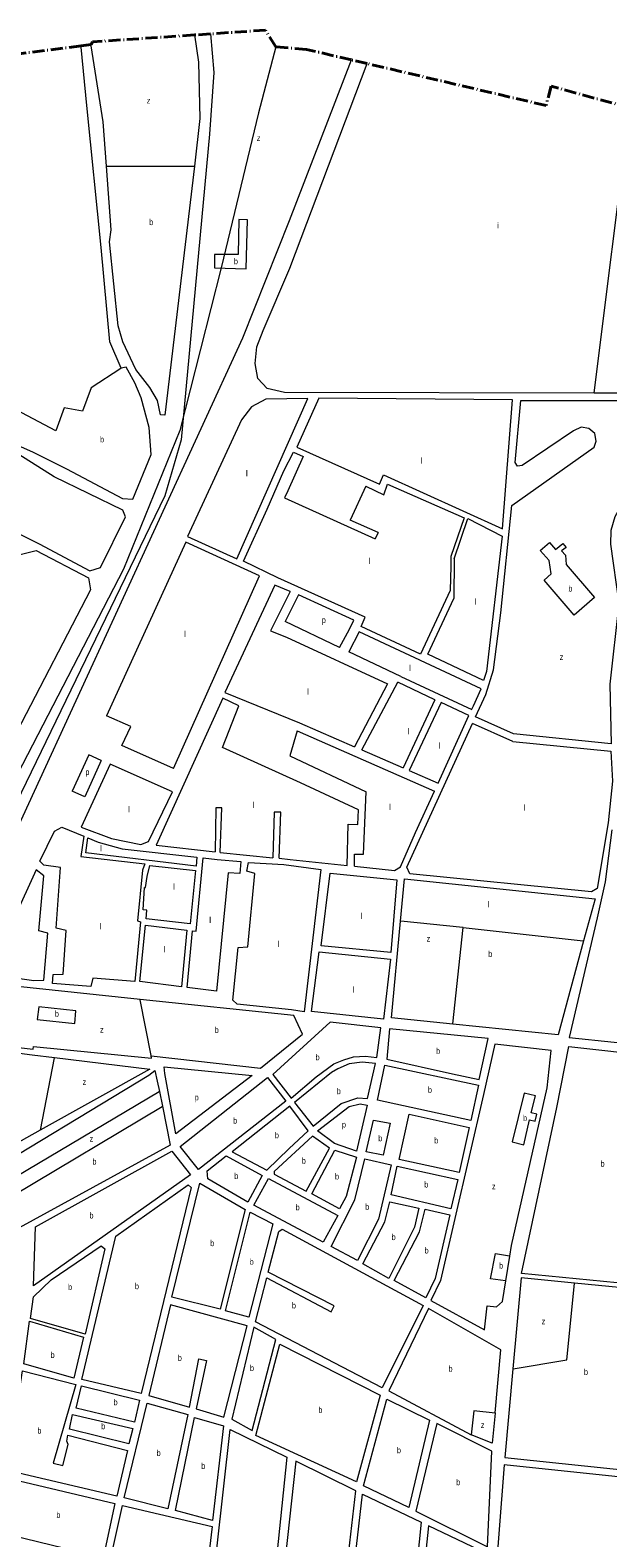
# Model space of a CAD drawing. Extents: x 639657 to 671642, y 222838 to 252123.
# Drawn here: x 650568 to 651529, y 249227 to 251734 of the extents above; entities that cross this region are included whole.
import ezdxf

# ---------------------------------------------------------------- set-up
doc = ezdxf.new("R2010")
doc.units = 0
doc.header["$LTSCALE"] = 4
doc.linetypes.add('DOT_DASHED', pattern=[7.7, 5, -1.2, 0.3, -1.2])
for name, color, linetype, lineweight in [('1', 7, 'Continuous', 13), ('21', 7, 'Continuous', 13), ('4', 7, 'DOT_DASHED', 40), ('57', 7, 'Continuous', 35)]:
    doc.layers.add(name, color=color, linetype=linetype, lineweight=lineweight)
doc.layers.add('7', color=7, linetype='Continuous')

msp = doc.modelspace()

# ---------------------------------------------------------------- linework, layer by layer
at = {"layer": '1'}
for p, q in [((651022.534, 251025.498), (650996.831, 250968.191)), ((650996.831, 250968.191), (650991.702, 250956.694)), ((651126.739, 250976.285), (651100.554, 250919.799)), ((650991.702, 250956.694), (651142.14, 250888.441)), ((651147.339, 250899.362), (651100.554, 250919.799)), ((651273.44, 250855.25), (651296.38, 250922.23)), ((651147.339, 250899.362), (651142.14, 250888.441)), ((651273.44, 250855.25), (651273.412, 250789.632)), ((651000.903, 250801.258), (650968.026, 250735.47)), ((651014.698, 250795.242), (650992.53, 250750.887)), ((651083.049, 250708.025), (650992.53, 250750.887)), ((651083.049, 250708.025), (651099.383, 250738.481)), ((651115.519, 250734.12), (651098.663, 250700.632)), ((651184.96, 250659.77), (651098.663, 250700.632)), ((651184.96, 250659.77), (651302.849, 250604.591)), ((651119.913, 250537.737), (651179.824, 250650.134)), ((651241.761, 250621.112), (651179.824, 250650.134)), ((651241.761, 250621.112), (651188.624, 250507.908)), ((651251.99, 250616.319), (651199.021, 250503.394)), ((651298.29, 250594.624), (651251.99, 250616.319)), ((651303.203, 250605.365), (651305.776, 250610.992)), ((651247.037, 250482.549), (651298.29, 250594.624)), ((651302.849, 250604.591), (651303.203, 250605.365)), ((651372.6, 250564.2), (651309.313, 250592.462)), ((651012.526, 250569.33), (651240.906, 250469.143)), ((651016.41, 250582.67), (651107.856, 250542.971)), ((651371.4, 250551.74), (651304.221, 250581.317)), ((651119.913, 250537.737), (651188.624, 250507.908)), ((650701.425, 250513.803), (650653.418, 250409.014)), ((650805.341, 250468.037), (650701.425, 250513.803)), ((651199.021, 250503.394), (651247.037, 250482.549)), ((650845.891, 250359.361), (650844.357, 250344.121)), ((650884.404, 250366.79), (650971.905, 250358.392)), ((650767.52, 250345.44), (650843.654, 250337.132)), ((651446.49, 250063.62), (651271.221, 250081.624)), ((650571.8, 250030.6), (650608.784, 250026.134)), ((651385.13, 249659.49), (651371.395, 249508.303)), ((651341.863, 249435.427), (651351.37, 249539.82)), ((651341.863, 249435.427), (651341.776, 249434.557))]:
    msp.add_line(p, q, dxfattribs=at)
for points in [[(650868.558, 251728.311), (650873.94, 251663.96), (650866.91, 251561.41), (650819.54, 251053.22), (650792.31, 250960.32), (650503.6, 250364.17), (650397.41, 250169.26), (650436.51, 250167.22), (650922.17, 251222.64), (650999.81, 251417.78), (651103.042, 251685.015)], [(650841.676, 251726.488), (650848.34, 251681.08), (650850.95, 251587.37), (650841.626, 251508.588)], [(650719.99, 251172.42), (650701.18, 251216.42), (650686.79, 251372.84), (650662.52, 251609.21), (650653.43, 251706.344), (650653.243, 251708.344)], [(650695.569, 251508.588), (650690.09, 251582.2), (650670.087, 251708.47), (650669.77, 251710.47)], [(651506.632, 251130.988), (650991.55, 251131.69), (650962.56, 251138.73), (650947.27, 251155.44), (650942.47, 251180.36), (650945.4, 251207.87), (650955.85, 251235.19), (651000.24, 251338.48), (651129.262, 251678.874)], [(651639.899, 251585.126), (651635.23, 251566.32), (651635.56, 251556.65), (651642.6, 251551.42), (651693.7, 251527.7), (651600.79, 251130.86), (651506.632, 251130.988)], [(650841.626, 251508.588), (650792.58, 251094.19), (650785.49, 251094.6), (650780.27, 251118.65), (650767.33, 251140.32), (650744.05, 251170.12), (650722.66, 251216.48), (650715.07, 251242.89), (650700.72, 251382.55), (650703.46, 251402.55), (650695.569, 251508.588)], [(650438.466, 251107.379), (650456.62, 251099.69), (650513.21, 251067.4), (650542.48, 251046.85), (650573.67, 251032.54), (650628.95, 251004.98), (650721.88, 250955.61), (650739.06, 250954.58), (650769.57, 251029.02), (650766.65, 251073.7), (650752.99, 251122.87), (650742.61, 251148.2), (650728.14, 251174.16), (650719.99, 251172.42)], [(650334.663, 250945.634), (650451.28, 250936.15), (650517.94, 250912.7), (650583.33, 250880.44), (650667.87, 250835.56), (650685.47, 250841.19), (650727.11, 250925.33), (650722.36, 250936.05), (650608.15, 250991.81), (650479.68, 251072.68), (650442.25, 251091.7), (650405.34, 251107.088), (650366.98, 251123.08)], [(651375.4, 251015.45), (651384.83, 251118.69), (651600.45, 251118.4), (651570.94, 250984.21), (651564.1, 250966.67), (651540.69, 250925.01), (651534.23, 250902.73), (651533.99, 250879.52), (651547.35, 250780.97), (651532.62, 250647.02), (651534.79, 250547.7), (651372.6, 250564.2)], [(651309.313, 250592.462), (651326.27, 250629.58), (651338.94, 250670.72), (651351.54, 250765.36), (651369.5, 250943.96), (651506.45, 251040.96), (651509.77, 251051.02), (651507.54, 251063.72), (651497.96, 251072.2), (651485.1, 251074.05), (651471.94, 251068.17), (651386.94, 251010.6), (651378.99, 251009.4), (651375.4, 251015.45)], [(650962.68, 250938.03), (650990.51, 251001.51), (651006.65, 251033), (651022.534, 251025.498)], [(651126.739, 250976.285), (651156.88, 250962.05), (651163.07, 250979.61), (651290.37, 250923.59), (651268.42, 250859.42)], [(651267.083, 250802.702), (651217.67, 250696.68), (651119.16, 250742.82), (651125.55, 250758.45), (650980.57, 250823.59), (650923.19, 250851.76), (650962.68, 250938.03)], [(651296.38, 250922.23), (651353.73, 250892.98), (651327.75, 250667.82), (651322.54, 250653.03), (651230.132, 250697.074), (651273.412, 250789.632)], [(650468.73, 250842.08), (650578.63, 250869.25), (650665.75, 250823.52), (650669.03, 250803.98), (650546.19, 250567.94)], [(650806.853, 250506.475), (650950.11, 250827.13), (650827.53, 250882.85), (650695.622, 250594.447)], [(651268.42, 250859.42), (651268.039, 250843.28), (651267.083, 250802.702)], [(651000.903, 250801.258), (650975.28, 250811.52), (650892.23, 250632.96), (651016.41, 250582.67)], [(651099.383, 250738.481), (651106.82, 250753.48), (651014.698, 250795.242)], [(650968.026, 250735.47), (650994.92, 250725.09), (651162.82, 250647.6), (651107.856, 250542.971)], [(651305.776, 250610.992), (651318.563, 250638.954), (651115.519, 250734.12)], [(651114.325, 250438.006), (651018.39, 250483.12), (650888.2, 250541.65), (650915.49, 250610.69), (650888.82, 250623.72), (650778.27, 250379.37), (650875.99, 250367.893)], [(650806.853, 250506.475), (650721.023, 250545.187), (650735.723, 250576.702), (650695.622, 250594.447)], [(651012.526, 250569.33), (651000.5, 250528.04), (651127.588, 250468.048)], [(651371.4, 250551.74), (651534.23, 250535.66), (651536.92, 250485.77), (651529.73, 250416.63), (651511.37, 250307.39), (651501.86, 250301.9), (651199.81, 250331.45), (651195.2, 250342.68), (651304.221, 250581.317)], [(650686.723, 250520.278), (650665.895, 250529.451), (650638.271, 250469.056)], [(650686.723, 250520.278), (650659.421, 250459.746), (650638.271, 250469.056)], [(650653.418, 250409.014), (650703.5, 250390.32), (650752.71, 250380.58), (650765.37, 250385.34), (650805.341, 250468.037)], [(651107.783, 250344.088), (651174.74, 250336.87), (651184.47, 250343.22), (651209.35, 250400.14), (651240.906, 250469.143)], [(651107.783, 250344.088), (651107.783, 250364.5), (651123.184, 250364.5), (651127.588, 250468.048)], [(650884.404, 250366.79), (650887.277, 250441.537), (650877.477, 250441.537), (650875.99, 250367.893)], [(650982.397, 250357.386), (650985.28, 250433.833), (650974.08, 250433.833), (650971.905, 250358.392)], [(651095.834, 250345.376), (651097.283, 250414.224), (651113.384, 250413.523), (651114.325, 250438.006)], [(650759.24, 250348.16), (650755.19, 250337.41), (650747.06, 250253.41), (650751.79, 250251.49), (650742.62, 250152.66), (650672.59, 250158.04), (650669.41, 250144.28), (650605.39, 250149.46), (650606.85, 250164.29), (650623.39, 250164.55), (650628.33, 250237.38), (650611.57, 250240.98), (650619.22, 250342.17), (650591.29, 250346.17), (650584.83, 250352.81), (650608.96, 250402.5), (650621.39, 250409.41), (650657.479, 250394.247)], [(650657.479, 250394.247), (650652.663, 250360.516), (650759.24, 250348.16)], [(650844.357, 250344.121), (650661.297, 250366.275), (650664.625, 250391.245)], [(650664.625, 250391.245), (650681.82, 250384.02), (650721.59, 250373.18), (650845.891, 250359.361)], [(651536.06, 250404.859), (651524.81, 250318.44), (651511.7, 250258.59), (651464.84, 250059.32), (651614.58, 250043.81), (651636.5, 250260.1), (651650.02, 250259.53), (651659.791, 250403.293)], [(650761.257, 250256.55), (650762.69, 250271.06), (650756.67, 250271.48), (650758.93, 250309.07), (650760.43, 250309.07), (650763.17, 250326.91), (650767.52, 250345.44)], [(650843.654, 250337.132), (650834.706, 250248.217), (650761.257, 250256.55)], [(650829.547, 250142.518), (650838.304, 250236.699), (650844.78, 250235.979), (650856.483, 250358.183)], [(650856.483, 250358.183), (650879.45, 250355.63), (650919.02, 250352.29), (650917.14, 250332.31), (650898.03, 250333.11), (650878.18, 250136.22), (650829.547, 250142.518)], [(650982.397, 250357.386), (651001, 250355.6), (651095.834, 250345.376)], [(651184.473, 250252.815), (651190.93, 250323.22), (651508.03, 250289.86), (651489.044, 250220.063), (651446.49, 250063.62)], [(650820.036, 250143.75), (650751, 250152.69), (650760.211, 250245.953)], [(650760.211, 250245.953), (650828.95, 250238.138), (650820.036, 250143.75)], [(651271.221, 250081.624), (651169.73, 250092.05), (651184.473, 250252.815)], [(650751.211, 250122.705), (650494.56, 250149.78), (650485.12, 250144.17), (650455.69, 250072.56), (650458.95, 250059.69), (650470.57, 250051.77), (650573.28, 250040.05), (650574.12, 250044.56), (650770.49, 250025.17), (650769.62, 250028.82), (650951.57, 250008.54)], [(650951.57, 250008.54), (651021.69, 250064.72), (651006.91, 250095.73), (650751.211, 250122.705)], [(650584.9, 249905.065), (650360.9, 249779.99), (650325.29, 249801.35), (650428.99, 250010.48), (650442.46, 250043.75), (650465.65, 250044.67), (650571.8, 250030.6)], [(651341.51, 250048.57), (651322.64, 249964.55), (651250.77, 249655.24), (651235.17, 249622.05), (651324.25, 249573.12), (651328.42, 249613.1), (651343.89, 249611.28), (651353.91, 249620.59), (651359.472, 249654.835), (651366.157, 249695.986)], [(651366.157, 249695.986), (651369, 249713.49), (651428.17, 249975.81), (651435.25, 250037.71), (651341.51, 250048.57)], [(650608.784, 250026.134), (650767.42, 250006.98), (650584.9, 249905.065)], [(650788.395, 249945.143), (650801.61, 249880.4), (650520.77, 249726.86), (650468.951, 249816.967), (650765.83, 249996.5), (650775.7, 250004.36)], [(650775.7, 250004.36), (650779.91, 249986.71), (650783.434, 249969.447), (650788.395, 249945.143)], [(651371.395, 249508.303), (651358.01, 249360.95), (651586.01, 249337.13), (651611.36, 249517.32), (651610.78, 249637.37), (651473.892, 249650.789), (651385.13, 249659.49)], [(651351.37, 249539.82), (651231.2, 249608.71), (651164.95, 249471.6), (651302.1, 249398.54)], [(651341.776, 249434.557), (651336.784, 249384.617), (651302.1, 249398.54)], [(651356.83, 249348.91), (651339.856, 249126.621), (651334.656, 249058.524), (651331.824, 249021.434)], [(651391.051, 248956.455), (651492.1, 248946.95), (651582.89, 249325.08), (651356.83, 249348.91)]]:
    msp.add_lwpolyline(points, dxfattribs=at)
for points in [[(650912.01, 250855.38), (651030.58, 251122.08), (650960.46, 251121.1), (650936.66, 251108.35), (650920.18, 251086.6), (650830.08, 250892.75)], [(651370.88, 251119.91), (651048.58, 251122.37), (651011.89, 251041.32), (651149.54, 250979.53), (651156.14, 250994.93), (651354.28, 250905.01)], [(650508.26, 250163.57), (650574.66, 250154.1), (650591.41, 250155.01), (650597.63, 250232.99), (650582.8, 250236.6), (650591.34, 250328.13), (650578.43, 250338.4), (650502.23, 250171.5)], [(650931.91, 250350.61), (650990.15, 250347.06), (651051.93, 250338.62), (651024.23, 250102.36), (651002.96, 250105.38), (650912.61, 250114.73), (650905.72, 250121.58), (650914.7, 250209.02), (650930.8, 250210.35), (650942.05, 250332.38), (650928.73, 250335.99)], [(651168.34, 250200.88), (651052.48, 250211.74), (651067.54, 250332.87), (651178.46, 250321.41)], [(651155.96, 250090.04), (651036.69, 250102.66), (651048.94, 250202.1), (651167.58, 250189.71)], [(651067.2, 250084.71), (650971.85, 249997.94), (651002.34, 249958.61), (651044.06, 249993.75), (651073.53, 250015.4), (651090.14, 250022.32), (651106.09, 250027.32), (651126.5, 250028.4), (651144.95, 250026.28), (651151.51, 250075.46)], [(651161.67, 250023.53), (651270.71, 249998.79), (651315.49, 249989.68), (651330.44, 250057.5), (651166.31, 250074.02)], [(651608.83, 250028.6), (651613.28, 249644.75), (651385.5, 249667.22), (651444.4, 249943.05), (651464.25, 250044.49)], [(650791.36, 250010.42), (650937.66, 249996.33), (650810.96, 249899.26), (650792.61, 249999.5)], [(651080.31, 250007.58), (651069.92, 250001.23), (651008.4, 249951.26), (651039.23, 249911.99), (651085.91, 249949.49), (651113.52, 249958.94), (651129.84, 249958.2), (651142.9, 250016.21), (651120.81, 250018.35), (651098.87, 250015.35)], [(651145.97, 249955.1), (651158.37, 250013.31), (651314.29, 249980.01), (651301.71, 249921.5)], [(650993.71, 249953.45), (650848.67, 249839.76), (650817.72, 249878.38), (650963.19, 249992.72)], [(651031.14, 249903.98), (651000.39, 249945.14), (650904.49, 249869.52), (650962.34, 249838.7), (650999.29, 249874.58)], [(651074.48, 249883.05), (651046.38, 249904.1), (651098.84, 249944.44), (651117.26, 249948.87), (651128.87, 249947.03), (651111.51, 249870.66)], [(651139.742, 249922.1), (651167.46, 249916.708), (651155.852, 249863.72), (651127.556, 249869.527)], [(651182.26, 249856.38), (651198.78, 249931.67), (651298.59, 249909.67), (651282.07, 249835.02)], [(650974.34, 249832.4), (651027.73, 249803.88), (651066.17, 249875.47), (651038.09, 249895.23), (650974.37, 249836.69)], [(650835.29, 249831.02), (650573.83, 249646.43), (650577.17, 249744.8), (650803.92, 249870.51)], [(650930.46, 249785.38), (650863.84, 249824.42), (650863.05, 249837.74), (650894.35, 249862.7), (650954.56, 249829.93)], [(651036.99, 249799.66), (651075.43, 249872.32), (651111.17, 249860.57), (651094.14, 249794.94), (651083.15, 249774.45)], [(651108.57, 249789.46), (651125.15, 249857.45), (651168.82, 249847.47), (651147.7, 249757.33), (651112.66, 249688.34), (651069.31, 249711.85)], [(651168.82, 249797.87), (651179.14, 249845.41), (651279.81, 249823.41), (651268.21, 249774.57)], [(650752.9, 249467.55), (650654.18, 249490.44), (650711.17, 249729.02), (650831.33, 249814.29), (650836.47, 249809.96)], [(650884.55, 249607.54), (650804.29, 249627.75), (650850.91, 249817.4), (650925.88, 249773.38)], [(650964.63, 249825.15), (651080.46, 249763.48), (651055.94, 249719.05), (650940.31, 249780.38)], [(651158.48, 249752.9), (651166.56, 249786.25), (651214.95, 249775.88), (651207.71, 249744.26), (651165.3, 249658.68), (651121.94, 249683.04)], [(650932.4, 249594.17), (650893.35, 249604.7), (650934.23, 249768.82), (650972.16, 249749.49)], [(651216.16, 249736.16), (651225.49, 249773.82), (651266.58, 249764.25), (651241.94, 249658.4), (651226.76, 249626.71), (651173.7, 249655.09)], [(651153.96, 249477.1), (650943.32, 249586.8), (650961.99, 249659.96), (651069.39, 249603.18), (651074.02, 249613.1), (650964.62, 249669.18), (650982.19, 249736.97), (650987.37, 249740.59), (651222.36, 249614.01)], [(650659.98, 249566.03), (650568.8, 249592.11), (650574.16, 249628.17), (650603.54, 249656.36), (650686.37, 249713.05), (650692.78, 249707.86)], [(650929.31, 249580.22), (650801.86, 249614.87), (650765.77, 249463.83), (650833.57, 249444.76), (650849.28, 249525.02), (650861.73, 249522.16), (650844.73, 249441.9), (650890.42, 249428.33)], [(650641.09, 249492.67), (650558.06, 249516.55), (650567.49, 249587.82), (650657.37, 249560.89)], [(650940.37, 249577.73), (650903.82, 249424.51), (650937.83, 249405.75), (650976.89, 249557.47)], [(650983.51, 249549.41), (651150.41, 249464.62), (651111.04, 249320.41), (650943.76, 249397.74)], [(650631.34, 249397.97), (650730.4, 249372.67), (650712.83, 249296.54), (650530.64, 249339.24), (650555.85, 249504.96), (650644.68, 249482.55), (650606.875, 249351.519), (650622.65, 249347.53), (650631.66, 249382.72), (650629.32, 249387.89)], [(650644.78, 249443.04), (650653.84, 249480.44), (650750.47, 249456.39), (650741.89, 249419.92)], [(651198.33, 249278.11), (651122.69, 249314.05), (651161.85, 249458.26), (651232.77, 249423.15)], [(650732.87, 249383.66), (650633.74, 249408.27), (650639.03, 249432.52), (650739.03, 249409.19)], [(650797.37, 249275.66), (650724.84, 249293.68), (650762.91, 249451.38), (650830.71, 249432.31)], [(650871.83, 249256.12), (650810.25, 249272.79), (650841.86, 249427.74), (650889.91, 249413.93)], [(650958.27, 248999.95), (650856.68, 249010.84), (650901.05, 249407.43), (650995.13, 249361.78)], [(651336.46, 249371.31), (651244.84, 249417.44), (651209.76, 249271.97), (651329.18, 249212.52)], [(650971.59, 248999.45), (651073.38, 248988.45), (651110.31, 249305.58), (651010.3, 249354.87)], [(650689.9, 249193.97), (650516.31, 249236.41), (650529.28, 249327.22), (650709.54, 249284.53)], [(650854.44, 249107.32), (650689.53, 249129.52), (650700.15, 249182.31), (650825.9, 249151.96), (650827.67, 249160.76), (650702.13, 249191.32), (650721.98, 249281.24), (650871.34, 249246.03)], [(651121.51, 249300.08), (651218.71, 249253.56), (651190.47, 248975.38), (651085.21, 248985.75)], [(651231, 249247.64), (651202.49, 248975.9), (651309.26, 248965.97), (651327.77, 249201.12)]]:
    msp.add_lwpolyline(points, close=True, dxfattribs=at)
at = {"layer": '21'}
for points in [[(651506.632, 251130.988), (651506.694, 251131.488), (651565.842, 251604.885), (651565.904, 251605.385)], [(650695.569, 251508.588), (650696.068, 251508.588), (650841.126, 251508.588), (650841.626, 251508.588)], [(650719.99, 251172.42), (650719.49, 251172.09), (650670.012, 251139.459), (650655.321, 251101.02), (650624.81, 251106.673), (650611.25, 251068.233), (650460.953, 251147.373), (650438.747, 251107.879), (650438.466, 251107.379)], [(651288.896, 250242.217), (651288.396, 250242.268), (651184.973, 250252.764), (651184.473, 250252.815)], [(651271.221, 250081.624), (651271.276, 250082.124), (651288.896, 250242.217)], [(651288.896, 250242.217), (651488.545, 250220.118), (651489.044, 250220.063)], [(650769.62, 250028.82), (650769.522, 250029.32), (650751.309, 250122.205), (650751.211, 250122.705)], [(650608.784, 250026.134), (650608.685, 250025.634), (650584.999, 249905.566), (650584.9, 249905.065)], [(650783.434, 249969.447), (650782.934, 249969.15), (650526.187, 249816.499), (650539.247, 249796.175), (650787.895, 249944.844), (650788.395, 249945.143)], [(651359.472, 249654.835), (651358.972, 249654.904), (651334.329, 249658.304), (651342.31, 249700.404), (651365.657, 249696.079), (651366.157, 249695.986)], [(651371.395, 249508.303), (651371.896, 249508.386), (651461.297, 249523.294), (651473.843, 249650.289), (651473.892, 249650.789)], [(651341.776, 249434.557), (651306.312, 249438.331), (651302.1, 249398.54)]]:
    msp.add_lwpolyline(points, dxfattribs=at)
for points in [[(650874.832, 251339.004), (650927.945, 251337.873), (650930.205, 251419.274), (650915.797, 251419.84), (650914.384, 251361.615), (650874.832, 251361.615)], [(651507.37, 250791.056), (651473.543, 250761.934), (651423.481, 250820.003), (651435.09, 250830.165), (651431.462, 250852.666), (651416.952, 250869.361), (651432.188, 250882.427), (651442.345, 250870.813), (651454.679, 250880.975), (651459.758, 250874.442), (651452.502, 250868.635), (651459.032, 250861.377), (651459.758, 250846.134)], [(650580.258, 250089.459), (650642.997, 250082.89), (650644.448, 250103.94), (650582.778, 250110.473)], [(651370.204, 249886.053), (651389.832, 249881.143), (651398.901, 249922.519), (651408.333, 249920.341), (651411.235, 249931.955), (651401.803, 249934.133), (651409.059, 249962.441), (651390.195, 249966.796)]]:
    msp.add_lwpolyline(points, close=True, dxfattribs=at)
at = {"layer": '4'}
for points in [[(650841.676, 251726.488), (650672.12, 251714.99), (650669.77, 251710.47), (650653.243, 251708.344)], [(651103.042, 251685.015), (651028.38, 251702.5), (650976.92, 251706.59), (650959.67, 251734.49), (650868.558, 251728.311), (650841.676, 251726.488)], [(650653.243, 251708.344), (650473.49, 251685.22), (650421.473, 251696.484), (650404.697, 251700.116)], [(651565.904, 251605.385), (651435.16, 251641.18), (651426.47, 251609.27), (651129.262, 251678.874), (651103.042, 251685.015)]]:
    msp.add_lwpolyline(points, dxfattribs=at)
at = {"layer": '57', "lineweight": 13}
msp.add_lwpolyline([(650976.92, 251706.59), (650948.417, 251596.85), (650886.075, 251339.041), (650817.499, 251068.757), (650723.986, 250837.976), (650379.029, 250172.663), (650296.945, 250007.374), (650199.276, 249816.096), (650168.106, 249776.593), (650134.857, 249759.961), (650037.188, 249587.395), (649818.992, 249148.704)], dxfattribs=at)

# ---------------------------------------------------------------- texts
at = {"layer": '7'}
for s, width, p in [('z', 0.8, (650762.392, 251612.6)), ('z', 0.8, (650945.459, 251550.418)), ('b', 0.75, (650766.439, 251410.339)), ('b', 0.75, (650907.322, 251345.222)), ('b', 0.75, (650684.703, 251049.014)), ('b', 0.75, (651463.658, 250801.027)), ('p', 0.75, (651053.589, 250748.595)), ('z', 0.8, (651449.237, 250687.169)), ('p', 0.75, (650660.355, 250495.996)), ('z', 0.8, (651227.952, 250218.99)), ('b', 0.75, (651330.412, 250193.42)), ('b', 0.75, (650609.553, 250093.795)), ('z', 0.8, (650684.713, 250067.645)), ('b', 0.75, (650875.526, 250066.92)), ('b', 0.75, (651243.61, 250031.85)), ('b', 0.75, (651043.236, 250021.66)), ('z', 0.8, (650655.694, 249980.543)), ('p', 0.75, (650842.145, 249954.84)), ('b', 0.75, (651078.467, 249965.17)), ('b', 0.75, (651230.086, 249967.405)), ('b', 0.75, (650906.064, 249916.24)), ('p', 0.75, (651087.073, 249909.765)), ('b', 0.75, (651388.279, 249920.45)), ('z', 0.8, (650667.303, 249886.181)), ('b', 0.75, (650975.486, 249891.92)), ('b', 0.75, (651147.602, 249886.974)), ('b', 0.75, (651240.47, 249883.345)), ('b', 0.75, (650672.131, 249848.189)), ('b', 0.75, (651020.314, 249849.555)), ('b', 0.75, (650907.931, 249824.04)), ('b', 0.75, (651075.531, 249823.385)), ('b', 0.75, (651517.172, 249844.62)), ('b', 0.75, (651224.037, 249809.99)), ('z', 0.8, (651336.501, 249806.802)), ('b', 0.75, (651010.095, 249772.1)), ('b', 0.75, (651125.769, 249772.895)), ('b', 0.75, (650667.177, 249758.47)), ('b', 0.75, (651169.735, 249722.465)), ('b', 0.75, (650867.908, 249712.47)), ('b', 0.75, (651224.523, 249700.265)), ('b', 0.75, (650933.616, 249681.495)), ('b', 0.75, (651348.375, 249675.108)), ('b', 0.75, (650631.495, 249639.54)), ('b', 0.75, (650742.669, 249640.92)), ('b', 0.75, (651003.81, 249608.845)), ('z', 0.8, (651419.211, 249582.51)), ('b', 0.75, (650602.466, 249526.454)), ('b', 0.75, (650814.092, 249521.6)), ('b', 0.75, (650934.109, 249504.806)), ('b', 0.75, (651264.308, 249503.625)), ('b', 0.75, (651489.587, 249498.31)), ('b', 0.75, (650707.191, 249448.003)), ('b', 0.75, (651047.9, 249434.91)), ('b', 0.75, (650580.538, 249400.75)), ('b', 0.75, (650686.615, 249408.09)), ('z', 0.8, (651317.997, 249409.989)), ('b', 0.75, (650778.885, 249363.52)), ('b', 0.75, (651178.554, 249368.185)), ('b', 0.75, (650853.008, 249341.93)), ('b', 0.75, (651277.005, 249314.98)), ('b', 0.75, (650612.057, 249260.595))]:
    msp.add_text(s, height=10, dxfattribs=dict(at, width=width)).set_placement(p)
for s, p in [('i', (651345.172, 251404.867)), ('l', (651218.058, 251013.69)), ('l', (650927.348, 250992.484)), ('l', (651130.995, 250846.742)), ('l', (651307.523, 250779.081)), ('l', (650824.323, 250725.368)), ('l', (651198.694, 250668.75)), ('l', (651028.921, 250629.554)), ('l', (651196.755, 250563.773)), ('l', (651248.03, 250539.547)), ('l', (650731.456, 250433.572)), ('l', (650938.956, 250440.83)), ('l', (651165.32, 250437.927)), ('l', (651388.782, 250436.475)), ('l', (650685.022, 250368.97)), ('l', (650806.185, 250305.094)), ('l', (651329.526, 250275.607)), ('l', (650866.403, 250249.929)), ('l', (651118.161, 250256.461)), ('l', (650683.571, 250239.041)), ('l', (650790.223, 250201.296)), ('l', (650980.311, 250210.006)), ('l', (651105.101, 250133.791))]:
    msp.add_text(s, height=10, dxfattribs=at).set_placement(p)

doc.saveas('drawing.dxf')
